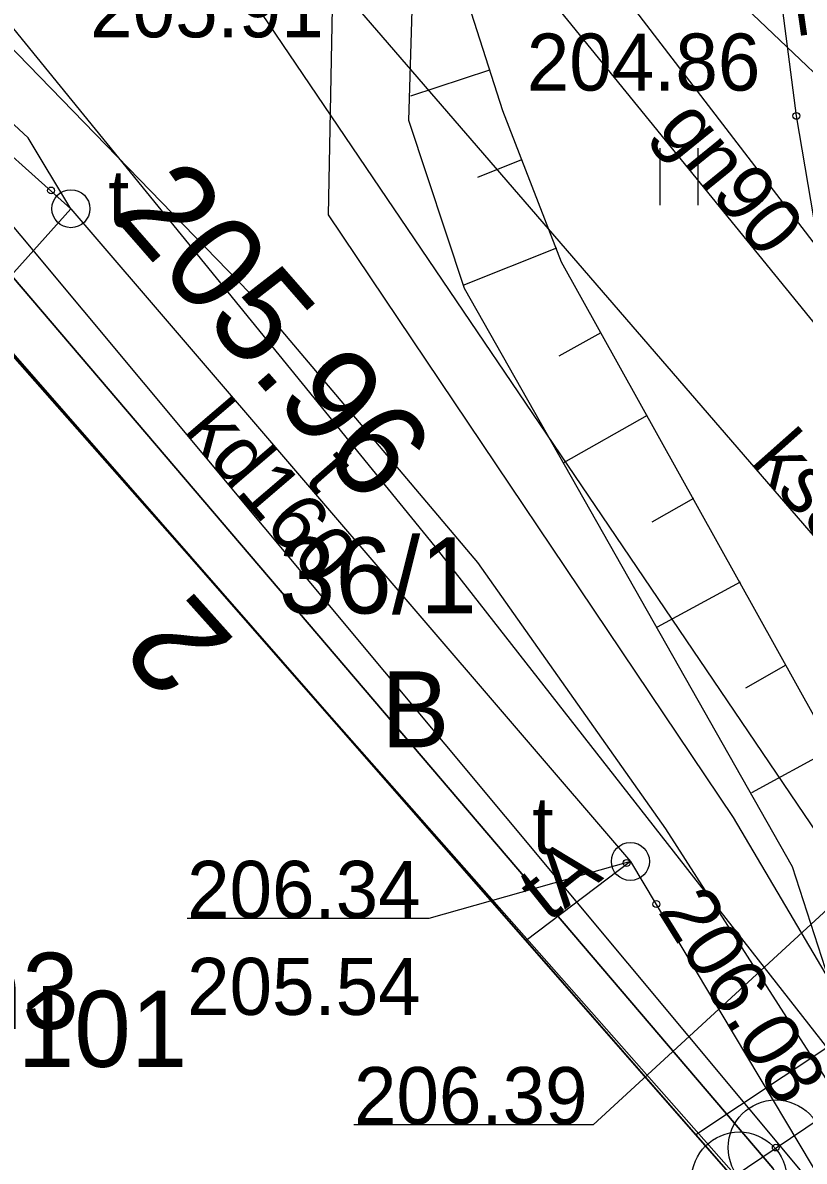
# Model space of a CAD drawing. Extents: x 6512606 to 6513347, y 6022524 to 6022728.
# Drawn here: x 6512828.62 to 6512838.88, y 6022634.38 to 6022649.34 of the extents above; entities that cross this region are included whole.
import ezdxf

# ---------------------------------------------------------------- set-up
doc = ezdxf.new("R2010")
doc.units = 0
for name, color, linetype in [('121-Punkt osnowy szczegółowej', 7, 'Continuous'), ('210-oznaczenie konturu użytku gruntowego', 7, 'Continuous'), ('211-numer działki ewidencyjnej', 7, 'Continuous'), ('216-obręb ewidencyjny', 7, 'Continuous'), ('218-kontur użytku gruntowego', 7, 'Continuous'), ('219-działka ewidencyjna', 7, 'Continuous'), ('238-Punkt adresowy budynku', 7, 'Continuous'), ('312-budynek ewidencyjny', 7, 'Continuous'), ('312-oznaczenie budynku ewidencyjnego', 7, 'Continuous'), ('312-oznaczenie budynku ewidencyjnego-Atr117', 7, 'Continuous'), ('4', 7, 'Continuous'), ('820-Skarpa nieumocniona', 7, 'Continuous'), ('823-Szczyt skarpy nieumocninej', 7, 'Continuous'), ('824-Podnóże skarpy nieumocninej', 7, 'Continuous'), ('940-Trawnik symb. poj.', 7, 'Continuous'), ('chodnik (powierzchnia)', 7, 'Continuous'), ('Default', 7, 'Continuous'), ('przewód ciepłowniczy (linia)', 7, 'Continuous'), ('przewód elektroenergetyczny (linia)', 7, 'Continuous'), ('przewód gazowy (linia)', 7, 'Continuous'), ('przewód gazowy (linia)-Atr1', 7, 'Continuous'), ('przewód kanalizacyjny (linia)', 7, 'Continuous'), ('przewód kanalizacyjny (linia)-Atr1', 7, 'Continuous'), ('przewód telekomunikacyjny (linia)', 7, 'Continuous'), ('przewód telekomunikacyjny (linia)-Atr1', 7, 'Continuous'), ('przewód wodociągowy (linia)', 7, 'Continuous'), ('punkt o określonej wysokości (sieć gazowa)-Atr3', 7, 'Continuous'), ('punkt o określonej wysokości (sieć kanalizacyjna)-Atr3', 7, 'Continuous'), ('punkt o określonej wysokości (sieć telekomunikacyjna)', 7, 'Continuous'), ('punkt o określonej wysokości (sieć telekomunikacyjna)-Atr2', 7, 'Continuous'), ('punkt o określonej wysokości (sieć telekomunikacyjna)-Atr3', 7, 'Continuous'), ('punkt o określonej wysokości (sieć wodociągowa)-Atr2', 7, 'Continuous'), ('punkt wysokościowy sztuczny', 7, 'Continuous'), ('punkt wysokościowy sztuczny-Atr2', 7, 'Continuous'), ('właz okrągły - siec telekomunikacyjna (punkt)', 7, 'Continuous'), ('właz okrągły - siec telekomunikacyjna (punkt)-Atr17', 7, 'Continuous')]:
    doc.layers.add(name, color=color, linetype=linetype)

# ---------------------------------------------------------------- blocks, each defined once
blk = doc.blocks.new('PW01')
at = {"layer": 'Default'}
blk.add_circle((0, 0), 0.45, dxfattribs=at)
blk = doc.blocks.new('US22')
at = {"layer": 'Default'}
blk.add_circle((0, 0), 2.5, dxfattribs=at)
blk = doc.blocks.new('940P')
at = {"layer": 'Default'}
for p, q in [((-2.5, -3.75), (-2.5, 3.75)), ((2.5, -3.75), (2.5, 3.75))]:
    blk.add_line(p, q, dxfattribs=at)
blk = doc.blocks.new('PW02')
at = {"layer": 'Default'}
blk.add_circle((0, 0), 0.45, dxfattribs=at)
blk = doc.blocks.new('121')
at = {"layer": 'Default'}
for radius in [6.25, 0.45]:
    blk.add_circle((0, 0), radius, dxfattribs=at)

msp = doc.modelspace()

# ---------------------------------------------------------------- linework, layer by layer
at = {"layer": '216-obręb ewidencyjny'}
for points in [[(6512836.687, 6022675.173), (6512833.61, 6022675.02), (6512828.67, 6022670.98), (6512801.96, 6022670.34), (6512810.18, 6022663.28), (6512825.37, 6022649.66), (6512838.47, 6022634.29), (6512852.25, 6022608.25), (6512853.17, 6022604.51), (6512855.78, 6022583.95), (6512858.85, 6022571.74), (6512828.23, 6022562.62), (6512818.47, 6022559.72), (6512824.714, 6022553.406)], [(6512852.25, 6022608.25), (6512838.47, 6022634.29), (6512825.37, 6022649.66), (6512810.18, 6022663.28), (6512801.96, 6022670.34), (6512796.96, 6022674.74), (6512790.49, 6022674.74), (6512785.56, 6022674.74), (6512768.24, 6022674.27), (6512754.87, 6022673.72), (6512745.51, 6022673.33), (6512735.76, 6022672.94), (6512730.35, 6022672.71), (6512725.78, 6022672.95), (6512702.575, 6022674.177)]]:
    msp.add_lwpolyline(points, dxfattribs=at)
at = {"layer": '218-kontur użytku gruntowego'}
for points in [[(6512835.81, 6022651.74), (6512852.34, 6022636.01)], [(6512852.34, 6022636.01), (6512835.81, 6022651.74)], [(6512838.47, 6022634.29), (6512825.37, 6022649.66)], [(6512825.37, 6022649.66), (6512838.47, 6022634.29)], [(6512838.09, 6022634.07), (6512824.77, 6022649.17)], [(6512824.77, 6022649.17), (6512838.09, 6022634.07)]]:
    msp.add_lwpolyline(points, dxfattribs=at)
at = {"layer": '219-działka ewidencyjna'}
for points in [[(6512852.34, 6022636.01), (6512835.81, 6022651.74)], [(6512838.47, 6022634.29), (6512825.37, 6022649.66)], [(6512824.77, 6022649.17), (6512838.09, 6022634.07)]]:
    msp.add_lwpolyline(points, dxfattribs=at)
at = {"layer": '312-budynek ewidencyjny'}
msp.add_lwpolyline([(6512824.72, 6022649.31), (6512838.13, 6022633.96)], dxfattribs=at)
at = {"layer": '4'}
for points in [[(6512852.34, 6022636.01), (6512835.81, 6022651.74)], [(6512838.47, 6022634.29), (6512825.37, 6022649.66)], [(6512824.77, 6022649.17), (6512838.09, 6022634.07)]]:
    msp.add_lwpolyline(points, dxfattribs=at)
at = {"layer": '820-Skarpa nieumocniona'}
for p, q in [((6512834.75, 6022648.72), (6512833.71, 6022648.38)), ((6512835.17, 6022647.54), (6512834.59, 6022647.31)), ((6512835.63, 6022646.38), (6512834.4, 6022645.89)), ((6512836.21, 6022645.27), (6512835.66, 6022644.96)), ((6512836.82, 6022644.18), (6512835.72, 6022643.56)), ((6512837.43, 6022643.09), (6512836.88, 6022642.78)), ((6512838.04, 6022641.99), (6512836.95, 6022641.4)), ((6512838.64, 6022640.9), (6512838.11, 6022640.6)), ((6512839.25, 6022639.8), (6512838.19, 6022639.22))]:
    msp.add_line(p, q, dxfattribs=at)
at = {"layer": '823-Szczyt skarpy nieumocninej'}
msp.add_lwpolyline([(6512833.8, 6022651.69), (6512834.92, 6022648.19), (6512835.69, 6022646.2), (6512839.8, 6022638.81), (6512840.88, 6022636.68), (6512842.42, 6022630.86), (6512843.78, 6022626.35)], dxfattribs=at)
at = {"layer": '824-Podnóże skarpy nieumocninej'}
msp.add_lwpolyline([(6512843.78, 6022626.35), (6512842.81, 6022626.09), (6512839.81, 6022635.37), (6512839.21, 6022636.76), (6512838.73, 6022638.25), (6512834.42, 6022645.85), (6512833.69, 6022648.06), (6512833.8, 6022651.69)], dxfattribs=at)
at = {"layer": 'chodnik (powierzchnia)'}
msp.add_lwpolyline([(6512845.61, 6022610.5), (6512844.69, 6022613.44), (6512844.06, 6022613.28), (6512843.41, 6022615.01), (6512844.01, 6022615.23), (6512838.87, 6022629.83), (6512839.52, 6022630.32), (6512838.94, 6022631.84), (6512838.15, 6022631.88), (6512837.86, 6022632.79), (6512838.13, 6022633.96), (6512826.89, 6022646.81), (6512825.11, 6022648.85), (6512824.32, 6022649.76), (6512820.29, 6022654.03), (6512817.62, 6022656.88), (6512816.1, 6022658.5), (6512810.3, 6022663.44), (6512802.06, 6022670.47), (6512797.05, 6022674.74)], dxfattribs=at)
msp.add_lwpolyline([(6512832.77, 6022654.07), (6512832.63, 6022646.82), (6512837.95, 6022638.9), (6512839.21, 6022636.76), (6512839.81, 6022635.37), (6512842.81, 6022626.09), (6512843.78, 6022626.35), (6512842.42, 6022630.86), (6512840.88, 6022636.68), (6512839.84, 6022641.88), (6512838.78, 6022648.12), (6512838.09, 6022653.46), (6512836.3, 6022653.4), (6512834.86, 6022653.53), (6512833.61, 6022653.83)], close=True, dxfattribs=at)
at = {"layer": 'przewód ciepłowniczy (linia)'}
for points in [[(6512837.46, 6022634.73), (6512851.24, 6022643.89)], [(6512852.19, 6022643.78), (6512837.95, 6022634.17)]]:
    msp.add_lwpolyline(points, dxfattribs=at)
at = {"layer": 'przewód elektroenergetyczny (linia)'}
for points in [[(6512702.569, 6022673.878), (6512710.28, 6022673.25), (6512716.66, 6022675.97), (6512746.13, 6022674.3), (6512752.79, 6022674.32), (6512760.61, 6022675.35), (6512763.38, 6022676.06), (6512798.79, 6022676.04), (6512803.06, 6022673.02), (6512807.84, 6022668.96), (6512815.24, 6022662.53), (6512819.98, 6022657.77), (6512831.6, 6022645.79), (6512834.59, 6022642.25), (6512837.06, 6022638.75), (6512840.02, 6022634.13), (6512842.26, 6022630.04), (6512846.03, 6022621.35), (6512846.58, 6022618.9), (6512847.6, 6022616.23), (6512852.12, 6022605.09)], [(6512802.27, 6022673.66), (6512807.42, 6022670.09), (6512811.38, 6022666.87), (6512814.66, 6022663.43), (6512826.4, 6022651.65), (6512827.82, 6022650.09), (6512834.03, 6022642.46), (6512842.84, 6022631.19), (6512844.67, 6022626.95), (6512847.57, 6022619.87), (6512849.81, 6022612.67), (6512853.56, 6022600.08), (6512856.46, 6022588.83), (6512861.26, 6022569.82), (6512861.768, 6022567.654)]]:
    msp.add_lwpolyline(points, dxfattribs=at)
at = {"layer": 'przewód gazowy (linia)'}
msp.add_lwpolyline([(6512847.18, 6022613.76), (6512846.63, 6022615.41), (6512849.08, 6022617.22), (6512845.94, 6022626.61), (6512846.16, 6022628.38), (6512844.18, 6022631.79), (6512844.23, 6022632.26), (6512844.43, 6022634.25), (6512844.47, 6022634.75), (6512844, 6022635.91), (6512842.48, 6022639.61), (6512842.1, 6022640.54), (6512841.83, 6022641.94), (6512833.52, 6022652.16), (6512828.68, 6022655.12), (6512826.33, 6022655.65), (6512824.93, 6022656.06), (6512819.76, 6022660.64)], dxfattribs=at)
at = {"layer": 'przewód kanalizacyjny (linia)'}
for points in [[(6512809.75, 6022675.66), (6512823.01, 6022660.61), (6512831.4, 6022651.41), (6512840.81, 6022640.51)], [(6512825.42, 6022650.35), (6512838.94, 6022634.13)]]:
    msp.add_lwpolyline(points, dxfattribs=at)
at = {"layer": 'przewód telekomunikacyjny (linia)'}
for points in [[(6512803.2, 6022671.69), (6512803.68, 6022670.87), (6512814.12, 6022660.92), (6512820.62, 6022654.75), (6512822.04, 6022653.36), (6512827.37, 6022648.58), (6512829.25, 6022646.9)], [(6512829.25, 6022646.9), (6512828.69, 6022647.83), (6512819.07, 6022656.76), (6512812.33, 6022663.22), (6512803.2, 6022671.69)], [(6512829.25, 6022646.9), (6512828.01, 6022645.52)], [(6512829.25, 6022646.9), (6512836.6, 6022638.32)], [(6512836.6, 6022638.32), (6512835.23, 6022637.28)], [(6512836.6, 6022638.32), (6512844.42, 6022625.21), (6512848.91, 6022613.6), (6512851.86, 6022605.02), (6512853.91, 6022597.19), (6512860.14, 6022571.94), (6512860.33, 6022571.18)]]:
    msp.add_lwpolyline(points, dxfattribs=at)
at = {"layer": 'przewód wodociągowy (linia)'}
for points in [[(6512809.35, 6022681.88), (6512813.75, 6022676.76), (6512817.99, 6022672.04), (6512824.14, 6022665.03), (6512827.96, 6022660.57), (6512832.92, 6022654.39), (6512839.85, 6022645.35)], [(6512839.52, 6022638), (6512830.11, 6022651.9), (6512829.45, 6022652.92)]]:
    msp.add_lwpolyline(points, dxfattribs=at)
at = {"layer": 'punkt o określonej wysokości (sieć telekomunikacyjna)-Atr2'}
msp.add_lwpolyline([(6512836.6, 6022638.32), (6512833.95, 6022637.57), (6512830.777, 6022637.57)], dxfattribs=at)
at = {"layer": 'punkt o określonej wysokości (sieć wodociągowa)-Atr2'}
msp.add_lwpolyline([(6512839.52, 6022638), (6512836.11, 6022634.86), (6512832.969, 6022634.86)], dxfattribs=at)

# ---------------------------------------------------------------- block references
at = {"layer": '121-Punkt osnowy szczegółowej', "xscale": 0.1, "yscale": 0.10000000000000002}
for p in [(6512838.51, 6022634.56), (6512838.03, 6022634.14)]:
    msp.add_blockref('121', p, dxfattribs=at)
at = {"layer": '940-Trawnik symb. poj.', "xscale": 0.1, "yscale": 0.10000000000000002}
msp.add_blockref('940P', (6512837.24, 6022647.32), dxfattribs=at)
at = {"layer": 'punkt o określonej wysokości (sieć telekomunikacyjna)', "xscale": 0.1, "yscale": 0.10000000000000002}
for p in [(6512828.99, 6022647.14), (6512836.94, 6022637.76)]:
    msp.add_blockref('PW01', p, dxfattribs=at)
at = {"layer": 'punkt o określonej wysokości (sieć telekomunikacyjna)', "xscale": 0.1, "yscale": 0.09999999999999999, "rotation": 124.216}
msp.add_blockref('PW01', (6512836.55, 6022638.3), dxfattribs=at)
at = {"layer": 'punkt wysokościowy sztuczny', "xscale": 0.1, "yscale": 0.10000000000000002}
msp.add_blockref('PW02', (6512838.78, 6022648.12), dxfattribs=at)
at = {"layer": 'właz okrągły - siec telekomunikacyjna (punkt)', "xscale": 0.1}
for p, yscale, rotation in [((6512829.25, 6022646.9), 0.10000000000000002, -45.771999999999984), ((6512836.6, 6022638.32), 0.09999999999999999, 124.216)]:
    msp.add_blockref('US22', p, dxfattribs=dict(at, yscale=yscale, rotation=rotation))

# ---------------------------------------------------------------- texts
at = {"layer": '210-oznaczenie konturu użytku gruntowego'}
msp.add_text('B', height=1, dxfattribs=at).set_placement((6512833.33, 6022639.82))
at = {"layer": '211-numer działki ewidencyjnej'}
msp.add_text('36/1', height=1, dxfattribs=at).set_placement((6512831.98, 6022641.58))
at = {"layer": '238-Punkt adresowy budynku'}
msp.add_text('2', height=1.25, rotation=131.826, dxfattribs=at).set_placement((6512831.43, 6022641.21))
at = {"layer": '312-oznaczenie budynku ewidencyjnego'}
msp.add_text('101', height=1, dxfattribs=at).set_placement((6512828.55, 6022635.62))
at = {"layer": '312-oznaczenie budynku ewidencyjnego-Atr117'}
msp.add_text('h3', height=1, dxfattribs=at).set_placement((6512827.867, 6022636.12))
at = {"layer": '4'}
msp.add_text('36/1', height=1, dxfattribs=at).set_placement((6512831.98, 6022641.58))
at = {"layer": 'przewód gazowy (linia)-Atr1'}
msp.add_text('gn90', height=0.75, rotation=309.115, dxfattribs=at).set_placement((6512836.94, 6022647.95))
at = {"layer": 'przewód kanalizacyjny (linia)-Atr1'}
for s, rotation, p in [('kd160', 310.601, (6512830.72, 6022643.98)), ('ks500', 311.599, (6512838.17, 6022643.57))]:
    msp.add_text(s, height=0.75, rotation=rotation, dxfattribs=at).set_placement(p)
at = {"layer": 'przewód telekomunikacyjny (linia)-Atr1'}
for s, rotation, p in [('t', 311.377, (6512832.3, 6022643.34)), ('tA', 38.596, (6512835.52, 6022637.51))]:
    msp.add_text(s, height=0.75, rotation=rotation, dxfattribs=at).set_placement(p)
at = {"layer": 'punkt o określonej wysokości (sieć gazowa)-Atr3'}
msp.add_text('205.91', height=0.75, dxfattribs=at).set_placement((6512829.503, 6022649.152))
at = {"layer": 'punkt o określonej wysokości (sieć kanalizacyjna)-Atr3'}
msp.add_text('204.86', height=0.75, dxfattribs=at).set_placement((6512835.239, 6022648.452))
at = {"layer": 'punkt o określonej wysokości (sieć telekomunikacyjna)'}
msp.add_text('205.96', height=1.25, rotation=311.119, dxfattribs=at).set_placement((6512829.77, 6022646.83))
at = {"layer": 'punkt o określonej wysokości (sieć telekomunikacyjna)-Atr2'}
msp.add_text('206.34', height=0.75, dxfattribs=at).set_placement((6512830.777, 6022637.578))
msp.add_text('206.08', height=0.75, rotation=301.907, dxfattribs=at).set_placement((6512836.95, 6022637.67))
at = {"layer": 'punkt o określonej wysokości (sieć telekomunikacyjna)-Atr3'}
msp.add_text('205.54', height=0.75, dxfattribs=at).set_placement((6512830.777, 6022636.303))
at = {"layer": 'punkt o określonej wysokości (sieć wodociągowa)-Atr2'}
msp.add_text('206.39', height=0.75, dxfattribs=at).set_placement((6512832.969, 6022634.868))
at = {"layer": 'punkt wysokościowy sztuczny-Atr2'}
msp.add_text('207.12', height=0.75, rotation=278.221, dxfattribs=at).set_placement((6512838.41, 6022652.16))
at = {"layer": 'właz okrągły - siec telekomunikacyjna (punkt)-Atr17'}
for p in [(6512829.74, 6022646.66), (6512835.31, 6022638.42)]:
    msp.add_text('t', height=0.75, dxfattribs=at).set_placement(p)

doc.saveas('drawing.dxf')
